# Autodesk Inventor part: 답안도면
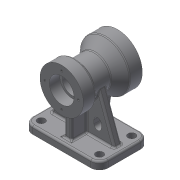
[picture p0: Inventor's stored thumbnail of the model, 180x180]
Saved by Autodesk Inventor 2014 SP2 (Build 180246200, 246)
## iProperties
Created: 2012-11
Part Number: 답안도면
Material: 일반
Document SubType Name: Modeling
Designer: 손기택
Density: 1 g/cm^3
Appearance: 기본값
Author: 손기택
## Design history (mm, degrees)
sketch "스케치1"
  geometry: L1 (-61, 40)-(61, 40); L2 (61, 40)-(61, -40); L3 (61, -40)-(-61, -40); L4 (-61, -40)-(-61, 40); 1 further point
  constraints: 8 end point, 2 parallel, 1 horizontal, 1 perpendicular
  dimensions: "d0" = 122 distance of L1.start L1.end; "d1" = 80 distance of L3.end L1.start; "d2" = 40 distance from line of L1 point (0, 0) (= 0.5 x d1); "d3" = 61 distance from line of L4 point (0, 0) (= 0.5 x d0)
extrude "돌출1" new body sketch "스케치1" distance "d4" = 12; taper "d5" = 0 deg
sketch "스케치3"
  geometry: L1 (-40, 120)-(-20, 120); L2 (-20, 120)-(-14.804, 111); L3 (-14.804, 111)-(13.315, 111); L4 (50, 125)-(50, 111); L5 (50, 111)-(30, 111); L6 (30, 111)-(30, 104); L7 (-40, 105)-(-40, 120); L8 (-54.476, 85)-(46.915, 85); L9 (40, 0)-(-40, 0) reference; L10 (13.315, 111)-(30, 125); L11 (50, 125)-(30, 125); L12 (27, 101)-(-23, 101); L13 (-23, 101)-(-23, 105); L14 (-23, 105)-(-40, 105); L15 (27, 101)-(30, 104); L16 (-40, 0)-(-40, 12) reference; 1 further point
  constraints: 28 end point, 5 parallel, 3 perpendicular, 1 horizontal
  dimensions: "d8" = 35 distance between parallel lines of L8 L1; "d9" = 85 distance between parallel lines of L9 L8; "d13" = 90 distance between parallel lines of L7 L4; "d14" = 20 distance of L1.start L1.end; "d15" = 60 deg angle of L3 L2; "d17" = 40 deg angle of L3 L10; "d18" = 40 distance from line of L4.start L8; "d19" = 20 distance of L4.start L10.end; "d20" = 26 distance between parallel lines of L8 L3; "d22" = 20 distance of L4.end L5.end; "d26" = 16 distance between parallel lines of L8 L12; "d27" = 3 distance from line of L12.start L6; "d28" = 20 distance between parallel lines of L8 L14; "d29" = 17 distance of L13.end L7.start; "d31" = 19 distance from line of L6.end L8; "d32" = 0 distance between parallel lines of L7 L16; "d33" = 26 distance between parallel lines of L5 L8
revolve "회전1" sketch "스케치3" stored, may be unused: angle "d34" = 90 deg
sketch "스케치4"
  geometry: L1 (-6, 30)-(6, 30); L2 (6, 30)-(6, -30); L3 (6, -30)-(-6, -30); L4 (-6, -30)-(-6, 30); L5 (-61, 40)-(61, 40) reference; L6 (61, -40)-(-61, -40) reference; 1 further point
  constraints: 8 end point, 2 parallel, 1 horizontal, 1 perpendicular
  dimensions: "d35" = 12 distance of L1.start L1.end; "d38" = 6 distance from line of point (0, 0) L2 (= 0.5 x d35); "d39" = 10 distance between parallel lines of L1 L5; "d40" = 10 distance between parallel lines of L6 L3
extrude "돌출2" join sketch "스케치4" stored distance "d41" = 12; taper "d42" = 0 deg
feature "면 기울기2" dims angle "d44" = 10 deg
sketch "스케치7"
  geometry: L1 (-61, 12)-(61, 12) reference; L2 (6, 12)-(6, 45.453) reference; L3 (51, 12)-(25.747, 81.382); L4 (61, 0)-(61, 12) reference; L5 (6, 12)-(6, 50.518) reference; L6 (6, 59.702)-(6, 50.518) reference; A1 r 40 centre (0, 85) between (6, 45.453) and (32.776, 62.071) reference; A2 r 26 centre (0, 85) between (6, 59.702) and (-6, 59.702) reference; 1 further point
  constraints: 2 end point, 2 point on circle, 2 point on line
  dimensions: "d45" = 10 distance from line of L4 L3.start; "d46" = 70 deg angle of L1 L3
extrude "돌출3" join sketch "스케치7" stored distance "d47" = 12; taper "d48" = 0 deg
sketch "스케치8"
  geometry: L1 (-24, 42)-(-24, 42); L2 (-18, 36)-(-18, 30); L3 (-24, 24)-(-24, 24); L4 (-30, 30)-(-30, 36); L5 (85.4, 0)-(-85.4, 0) reference; L6 (0, -25)-(0, 150) reference; A1 r 6 centre (-24, 36) between (-24, 42) and (-30, 36); A2 r 6 centre (-24, 36) between (-18, 36) and (-24, 42); A3 r 6 centre (-24, 30) between (-30, 30) and (-24, 24); A4 r 6 centre (-24, 30) between (-24, 24) and (-18, 30); 4 further points
  constraints: 8 end point, 8 point on circle, 8 tangent, 6 point on line, 4 centre point, 3 equal radius, 2 parallel, 1 horizontal, 1 perpendicular
  dimensions: "d50" = 12 distance of point (-18, 24) point (-30, 24); "d51" = 18 distance of point (-18, 42) point (-18, 24); "d53" = 6 radius of A1; "d54" = 30 distance from line of A3.centre L5; "d55" = 24 distance from line of A3.centre L6
extrude "돌출4" cut sketch "스케치8" stored distance "d56" = 12; taper "d57" = 0 deg
sketch "스케치9"
  geometry: L1 (-85.4, 0)-(85.4, 0) reference; L2 (0, -58)-(0, 68) reference; C1 r 6 at (47, 26); C2 r 6 at (47, -26); C3 r 6 at (-47, 26); C4 r 6 at (-47, -26); 1 further point
  constraints: 4 centre point, 3 symmetric about line, 3 other
  dimensions: "d58" = 26 vertical distance of C1.centre point (0, 0); "d59" = 47 horizontal distance of C1.centre point (0, 0); "d60" = 12 diameter of C1
extrude "돌출5" cut sketch "스케치9" distance "d61" = 12; taper "d62" = 0 deg
sketch "스케치10"
  geometry: C1 r 35 at (0, 0) reference; C2 r 20 at (0, 0) reference; A1 r 27 centre (0, 0) between (0, 27) and (-27, 0); 3 further points
  constraints: 4 point on circle, 1 centre point, 1 coincident
  dimensions: "d63" = 54 diameter of A1; "d64" = 54 distance of point (27, 0) A1.end; "d65" = 54 distance of point (0, -27) A1.start; "d66" = 27 horizontal distance of point (27, 0) point (0, -27) (= 0.5 x d65)
hole "구멍1" sketch "스케치10" at (0, 27), (-27, 0), (27, 0), (0, -27) diameter "d67" = 3.242; stored, may be unused: countersink angle "d71" = 90 deg, drill point angle "d73" = 118 deg; dims "d68" = 10, "d69" = 9.4, "d70" = 2, "d72" = 12
sketch "스케치11"
  geometry: C1 r 26 at (0, 0) reference; A1 r 33 centre (0, 0) between (0, -33) and (33, 0); 3 further points
  constraints: 4 point on circle, 1 centre point, 1 coincident
  dimensions: "d74" = 66 diameter of A1; "d75" = 66 distance of point (0, 33) A1.start; "d76" = 66 distance of point (-33, 0) A1.end; "d77" = 33 horizontal distance of point (0, 33) A1.end; "d78" = 33 horizontal distance of A1.start A1.end
hole "구멍2" sketch "스케치11" at (0, -33), (33, 0), (-33, 0), (0, 33) diameter "d79" = 3.242; stored, may be unused: countersink angle "d83" = 90 deg, drill point angle "d85" = 118 deg; dims "d80" = 10, "d81" = 9.4, "d82" = 2, "d84" = 12
fillet "모깎기1" dims "d86" = 14
fillet "모깎기3" dims "d91" = 3, "d92" = 3
fillet "모깎기4" dims "d93" = 3
node "솔리드1"
mirror "대칭1"
mirror "대칭2"
node "투영된 루프1"
